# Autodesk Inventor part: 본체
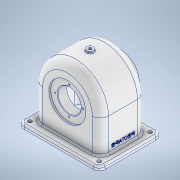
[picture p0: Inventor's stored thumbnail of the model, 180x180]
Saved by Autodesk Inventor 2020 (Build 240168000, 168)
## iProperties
Created: 2022-09
Part Number: 본체
Material: 알루미늄 6061
Document SubType Name: Modeling
Designer: Administrator
Density: 2.7 g/cm^3
Appearance: 알루미늄 - 평지
Mass: 785.035 g
Surface Area: 1042.06 cm^2
Volume: 290.754 cm^3
Author: Administrator
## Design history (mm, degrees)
sketch "스케치1"
  geometry: L1 (-70, 54)-(70, 54); L2 (70, 54)-(70, -54); L3 (70, -54)-(-70, -54); L4 (-70, -54)-(-70, 54); L5 (-70, 54)-(70, -54); L6 (70, 54)-(-70, -54); 1 further point
  constraints: 12 end point, 2 midpoint, 2 parallel, 1 horizontal, 1 perpendicular
  dimensions: "d0" = 140 distance of L1.start L1.end; "d1" = 108 distance of L3.end L1.start
extrude "돌출1" new body sketch "스케치1" distance "d2" = 7; taper "d3" = 0 deg
fillet "모깎기1" dims "d4" = 10
sketch "스케치2"
  geometry: A1 r 10 centre (60, -44) between (60, -54) and (70, -44) reference; 2 further points
  constraints: 1 coincident
hole "구멍1" sketch "스케치2" at (60, -44) diameter "d5" = 6.6; stored, may be unused: countersink angle "d9" = 90 deg, drill point angle "d11" = 150 deg; dims "d6" = 11, "d7" = 4, "d8" = 2, "d10" = 13
sketch "스케치3"
  geometry: L1 (60, 0)-(-60, 0) reference; L2 (57, 64)-(-57, 64); L3 (-57, 64)-(-57, 3.652); L4 (-57, 3.652)-(57, 3.652); L5 (57, 3.652)-(57, 64); C1 r 57 at (0, 64); 4 further points
  constraints: 8 end point, 2 midpoint, 2 parallel, 2 tangent, 1 centre point, 1 horizontal, 1 perpendicular, 1 vertical alignment
  dimensions: "d16" = 114 diameter of C1; "d17" = 64 distance from line of L1 C1.centre
extrude "돌출2" new body sketch "스케치3" stored distance "d18" = 78; taper "d19" = 0 deg
feature "쉘1" dims "d20" = 5
sketch "스케치4"
  geometry: L1 (52, -34)-(-52, -34) reference; L2 (-52, -34)-(-52, 34) reference; L3 (-52, 34)-(52, 34) reference; L4 (52, 34)-(52, -34) reference; 1 further point
extrude "돌출3" cut sketch "스케치4" extent not by distance; stored distance "d21" = 0; taper "d22" = 0 deg
feature "결합1"
  node "솔리드2"
node "작업 평면1"
sketch "스케치5"
  geometry: C1 r 6 at (0, 0); 1 further point
  constraints: 1 centre point, 1 coincident
  dimensions: "d24" = 12 diameter of C1
extrude "돌출4" join sketch "스케치5" stored distance "d25" = 78; taper "d26" = 0 deg
sketch "스케치6"
  geometry: C1 r 6 at (0, 0) reference; 2 further points
  constraints: 1 coincident
hole "구멍2" sketch "스케치6" at (0, 0) diameter "d27" = 5.1881; stored, may be unused: countersink angle "d31" = 90 deg, drill point angle "d33" = 150 deg; dims "d28" = 12, "d29" = 4, "d30" = 2, "d32" = 16
sketch "스케치7"
  geometry: L1 (-59.418, 64)-(67.035, 64); L2 (-36.086, 101.287)-(-20, 92); L3 (-20, 92)-(-20, 64); L4 (-34, 64)-(34, 64) reference; L5 (-36.086, 101.287)-(-36.086, 64); L6 (-34, 116)-(-34, 64) reference; L7 (36.934, 95)-(54, 95); L8 (54, 95)-(54, 64); L9 (54, 64)-(36.934, 64); L10 (36.934, 64)-(36.934, 95); L11 (39, 64)-(39, 121) reference; 3 further points
  constraints: 16 end point, 3 point on line, 2 horizontal, 2 parallel, 2 perpendicular, 1 vertical
  dimensions: "d34" = 64 distance from line of point (0, 0) L1; "d35" = 60 deg angle of L3 L2; "d36" = 56 diameter of L2.end L1; "d37" = 14 distance between parallel lines of L6 L3; "d38" = 15 distance between parallel lines of L8 L11; "d39" = 62 diameter of L7 L1
revolve "회전1" sketch "스케치7" stored, may be unused: angle "d40" = 90 deg
sketch "스케치8"
  geometry: C1 r 28 at (0, 0) reference; 2 further points
  constraints: 1 coincident
hole "구멍3" sketch "스케치8" at (0, 0) diameter "d41" = 40; stored, may be unused: countersink angle "d45" = 90 deg, drill point angle "d47" = 0 deg; dims "d42" = 12, "d43" = 4, "d44" = 2, "d46" = 16
sketch "스케치9"
  geometry: C1 r 20 at (0, 0) reference; 2 further points
  constraints: 1 coincident
hole "구멍4" sketch "스케치9" at (0, 0) diameter "d48" = 64; stored, may be unused: countersink angle "d52" = 90 deg, drill point angle "d54" = 0 deg; dims "d49" = 12, "d50" = 4, "d51" = 2, "d53" = 16
sketch "스케치10"
  geometry: C1 r 31 at (0, 0) reference; 2 further points
  constraints: 1 coincident
hole "구멍5" sketch "스케치10" at (0, 0) diameter "d55" = 35; stored, may be unused: countersink angle "d59" = 90 deg, drill point angle "d61" = 0 deg; dims "d56" = 12, "d57" = 40, "d58" = 16, "d60" = 16
sketch "스케치11"
  geometry: C1 r 20 at (0, 0) reference; 2 further points
  constraints: 1 vertical alignment
  dimensions: "d62" = 24 distance of C1.centre point (0, -24)
hole "구멍6" sketch "스케치11" at (0, -24) diameter "d63" = 2.459; stored, may be unused: countersink angle "d67" = 90 deg, drill point angle "d69" = 118 deg; dims "d64" = 7, "d65" = 40, "d66" = 16, "d68" = 9
sketch "스케치12"
  geometry: C1 r 1.23 at (0, 24) reference; 2 further points
  constraints: 1 coincident
hole "구멍7" sketch "스케치12" at (0, 24) diameter "d70" = 2.459; stored, may be unused: countersink angle "d74" = 90 deg, drill point angle "d76" = 118 deg; dims "d71" = 7, "d72" = 40, "d73" = 16, "d75" = 9
sketch "스케치13"
  geometry: L1 (0, 0)-(-57, 0) reference; L2 (7, -5)-(7, 83) reference; 2 further points
  constraints: 1 other
  dimensions: "d80" = 39 distance from line of L1 point (-10, 39); "d81" = 17 distance from line of point (-10, 39) L2
feature "엠보싱1" sketch "스케치13" dims "d0" = 140, "d1" = 108, "d82" = 0.5, "d83" = 0
fillet "모깎기2" dims "d84" = 14, "d85" = 9, "d86" = 1, "d87" = 0.6
chamfer "모따기1" distance "d88" = 1; stored, may be unused: second distance "d89" = 2, angle "d90" = 45 deg
fillet "모깎기3" dims "d91" = 3
node "솔리드1"
pattern_linear "직사각형 패턴1"
pattern_circular "원형 패턴1" dims angle "d78" = 360 deg
feature "A9D066F2-1C7D-4E18-AEED-F7BC21143FA4" dims "d5" = 6.6, "d6" = 11, "d7" = 4, "d8" = 2, "d9" = 90 deg, "d10" = 13, "d11" = 150 deg
other parameters: "d23" = 124
